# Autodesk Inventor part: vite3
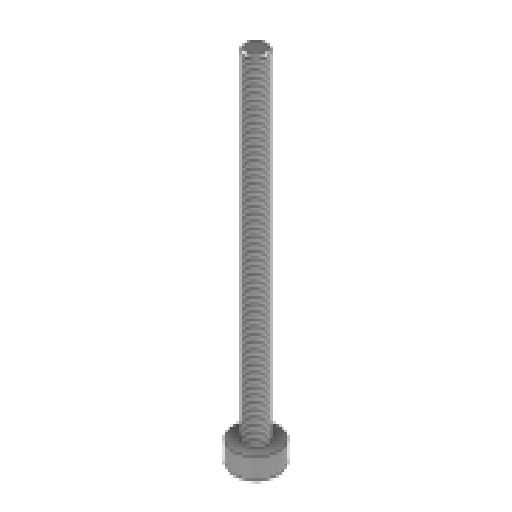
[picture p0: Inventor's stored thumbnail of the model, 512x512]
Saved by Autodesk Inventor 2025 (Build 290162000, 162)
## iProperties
Created: 2025-05
Part Number: vite3
Material: Acciaio inossidabile
Document SubType Name: Modeling
Designer: R5800u
Density: 8 g/cm^3
Appearance: Semilucidato
Author: R5800u
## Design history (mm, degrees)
sketch "Schizzo1"
  geometry: L1 (0, 0)-(4, 0); L2 (4, 0)-(4, 4); L3 (4, 4)-(2, 4); L4 (2, 4)-(2, 64); L5 (2, 64)-(0, 64); L6 (0, 64)-(0, 0)
  constraints: 12 end point, 4 perpendicular, 2 horizontal
  dimensions: "d0" = 4 distance of L1.start L1.end; "d1" = 4 distance of L1.end L2.end; "d3" = 60 distance of L3.end L4.end; "d4" = 2 distance between parallel lines of L4 L6
revolve "Rivoluzione1" sketch "Schizzo1" stored, may be unused: angle "d5" = 90 deg
sketch "Schizzo2"
  geometry: L1 (0, -1.5)-(-1.299, -0.75); L2 (-1.299, -0.75)-(-1.299, 0.75); L3 (-1.299, 0.75)-(0, 1.5); L4 (0, 1.5)-(1.299, 0.75); L5 (1.299, 0.75)-(1.299, -0.75); L6 (1.299, -0.75)-(0, -1.5); C1 r 4 at (0, 0) reference; 2 further points
  constraints: 12 end point, 1 coincident, 13 other
  dimensions: "d14" = 1.5 distance of L4.end L5.end
extrude "Estrusione1" cut sketch "Schizzo2" distance "d6" = 2; taper "d7" = 0 deg
chamfer "Smusso1" distance "d8" = 0.4; stored, may be unused: second distance "d9" = 2, angle "d10" = 45 deg
feature "Filettatura1" dims "d11" = 59.6, "d12" = 0
fillet "Raccordo1" dims "d13" = 0.5
node "Solido1"
